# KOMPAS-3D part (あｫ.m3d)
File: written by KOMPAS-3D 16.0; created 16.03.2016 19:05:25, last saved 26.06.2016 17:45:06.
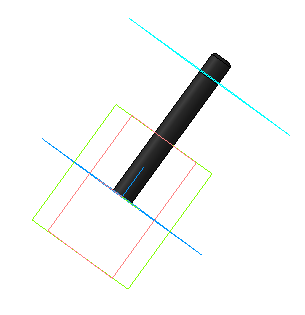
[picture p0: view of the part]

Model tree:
1. Эскиз:1
2. Операция выдавливания:1
     Расстояние 1 = 60
3. Смещенная плоскость:1
     Расстояние = 52
4. Эскиз:2
5. Вырезать элемент выдавливания:1
     Расстояние 1 = 0.5
6. Фаска:1
     Угол = 45; Длина 1 = 1; Длина 2 = 1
